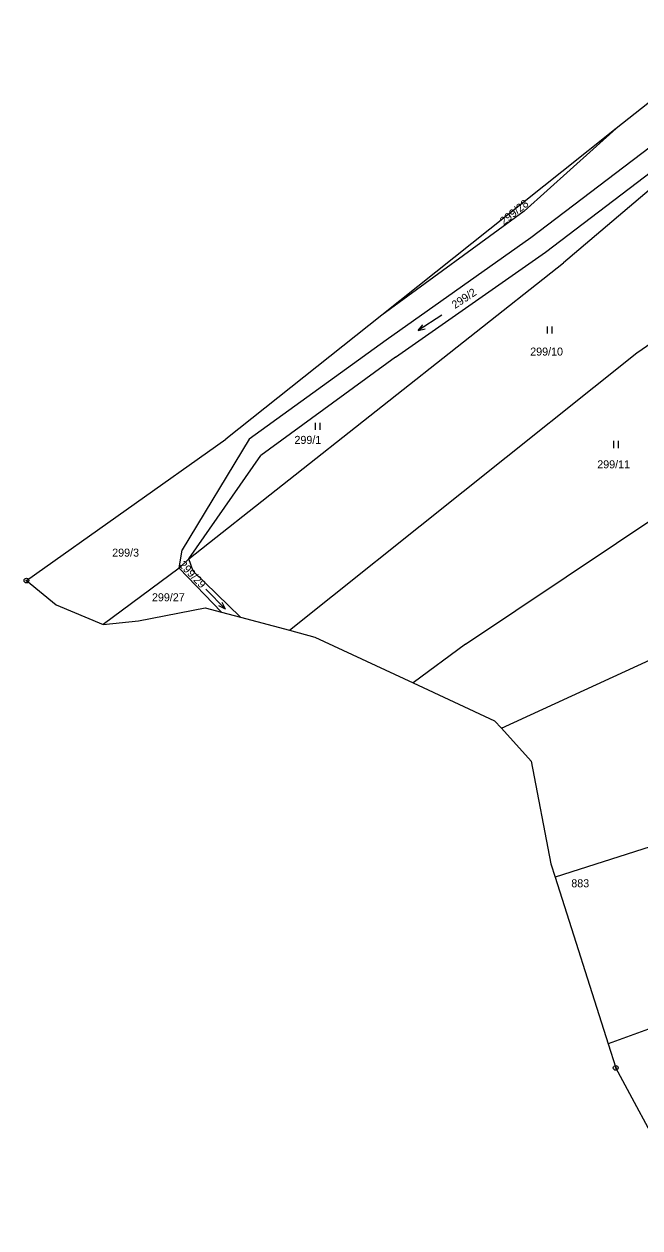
# Model space of a CAD drawing. Extents: x -762263 to -760336, y -1154405 to -1152076.
# Drawn here: x -761628.3 to -761497.7, y -1153957.4 to -1153701.8 of the extents above; entities that cross this region are included whole.
import ezdxf

# ---------------------------------------------------------------- set-up
doc = ezdxf.new("R2010")
doc.units = 0
for name, color, linetype in [('Vrstva 1', 7, 'Continuous'), ('Vrstva 13', 7, 'Continuous'), ('Vrstva 17', 7, 'Continuous'), ('Vrstva 18', 7, 'Continuous'), ('Vrstva 24', 7, 'Continuous'), ('Vrstva 25', 7, 'Continuous'), ('Vrstva 6', 7, 'Continuous')]:
    doc.layers.add(name, color=color, linetype=linetype)

msp = doc.modelspace()

# ---------------------------------------------------------------- linework, layer by layer
at = {"layer": 'Vrstva 1'}
for p, q in [((-761491.67, -1153725), (-761520.83, -1153747.19)), ((-761517.69, -1153750.19), (-761489.51, -1153728.71)), ((-761520.83, -1153747.19), (-761551.47, -1153768.91)), ((-761549.5, -1153772.51), (-761517.69, -1153750.19)), ((-761551.47, -1153768.91), (-761580.6, -1153789.9)), ((-761549.5, -1153772.51), (-761578.13, -1153793.41)), ((-761580.6, -1153789.9), (-761594.82, -1153813.41)), ((-761593.36, -1153815.36), (-761578.13, -1153793.41)), ((-761595.44, -1153817.33), (-761594.82, -1153813.41)), ((-761586.44, -1153826.67), (-761595.44, -1153817.33)), ((-761592.45, -1153817.96), (-761593.36, -1153815.36)), ((-761592.45, -1153817.96), (-761582.4, -1153827.73))]:
    msp.add_line(p, q, dxfattribs=at)
at = {"layer": 'Vrstva 13'}
for p, q in [((-761487.61, -1153711.97), (-761502.71, -1153723.99)), ((-761502.71, -1153723.99), (-761514.21, -1153733.15)), ((-761514.21, -1153733.15), (-761552.42, -1153763.57)), ((-761552.42, -1153763.57), (-761585.55, -1153789.95)), ((-761627.83, -1153819.95), (-761585.55, -1153789.95)), ((-761627.83, -1153819.95), (-761621.55, -1153825.1)), ((-761621.55, -1153825.1), (-761611.57, -1153829.29)), ((-761604.02, -1153828.47), (-761589.93, -1153825.71)), ((-761589.93, -1153825.71), (-761586.44, -1153826.67)), ((-761586.44, -1153826.67), (-761582.4, -1153827.73)), ((-761582.4, -1153827.73), (-761571.98, -1153830.52)), ((-761611.57, -1153829.29), (-761604.02, -1153828.47)), ((-761571.98, -1153830.52), (-761566.67, -1153831.95)), ((-761566.67, -1153831.95), (-761545.76, -1153841.68)), ((-761545.76, -1153841.68), (-761528.48, -1153849.72)), ((-761528.48, -1153849.72), (-761527.03, -1153851.32)), ((-761527.03, -1153851.32), (-761520.72, -1153858.29)), ((-761520.72, -1153858.29), (-761516.55, -1153880.13)), ((-761516.55, -1153880.13), (-761515.66, -1153882.92)), ((-761515.66, -1153882.92), (-761504.41, -1153918.34)), ((-761504.41, -1153918.34), (-761502.8, -1153923.42)), ((-761484.5, -1153957.41), (-761502.8, -1153923.42))]:
    msp.add_line(p, q, dxfattribs=at)
at = {"layer": 'Vrstva 24'}
for centre, radius in [((-761627.83, -1153819.95), 0.5), ((-761627.83, -1153819.95), 0.1), ((-761502.8, -1153923.42), 0.5), ((-761502.8, -1153923.42), 0.1)]:
    msp.add_circle(centre, radius, dxfattribs=at)
at = {"layer": 'Vrstva 25'}
for p, q in [((-761517.3, -1153767.5), (-761517.3, -1153766)), ((-761516.3, -1153767.5), (-761516.3, -1153766)), ((-761566.49, -1153787.96), (-761566.49, -1153786.46)), ((-761565.49, -1153787.96), (-761565.49, -1153786.46)), ((-761503.17, -1153791.81), (-761503.17, -1153790.31)), ((-761502.17, -1153791.81), (-761502.17, -1153790.31))]:
    msp.add_line(p, q, dxfattribs=at)
for points in [[(-761539.696, -1153763.612), (-761544.724, -1153766.888), (-761543.194, -1153766.488)], [(-761544.724, -1153766.888), (-761543.74, -1153765.65)], [(-761589.788, -1153821.766), (-761585.592, -1153826.054), (-761586.283, -1153824.632)], [(-761585.592, -1153826.054), (-761586.998, -1153825.332)]]:
    msp.add_lwpolyline(points, dxfattribs=at)
at = {"layer": 'Vrstva 6'}
for p, q in [((-761454.21, -1153701.79), (-761513.86, -1153752.5)), ((-761522.23, -1153741.49), (-761502.71, -1153723.99)), ((-761522.23, -1153741.49), (-761552.42, -1153763.57)), ((-761498.3, -1153771.59), (-761466.5, -1153749.37)), ((-761593.36, -1153815.36), (-761513.86, -1153752.5)), ((-761571.98, -1153830.52), (-761498.3, -1153771.59)), ((-761534.69, -1153833.47), (-761461.07, -1153784.2)), ((-761527.03, -1153851.32), (-761446.29, -1153814.02)), ((-761595.44, -1153817.33), (-761611.57, -1153829.29)), ((-761593.36, -1153815.36), (-761595.44, -1153817.33)), ((-761534.69, -1153833.47), (-761545.76, -1153841.68)), ((-761472.22, -1153869), (-761515.66, -1153882.92)), ((-761491.88, -1153913.75), (-761504.41, -1153918.34))]:
    msp.add_line(p, q, dxfattribs=at)

# ---------------------------------------------------------------- texts
at = {"layer": 'Vrstva 17'}
msp.add_text('883', height=1.7, dxfattribs=at).set_placement((-761512.214, -1153885.08))
at = {"layer": 'Vrstva 18'}
for s, rotation, p in [('299/28', 38.61736, (-761526.542, -1153744.557)), ('299/2', 33.68992, (-761536.899, -1153762.326)), ('299/29', 313.86628, (-761595.609, -1153816.722))]:
    msp.add_text(s, height=1.7, rotation=rotation, dxfattribs=at).set_placement(p)
for s, p in [('299/10', (-761520.935, -1153772.18)), ('299/1', (-761570.959, -1153790.93)), ('299/11', (-761506.71, -1153796.12)), ('299/3', (-761609.634, -1153814.87)), ('299/27', (-761601.2, -1153824.35))]:
    msp.add_text(s, height=1.7, dxfattribs=at).set_placement(p)

doc.saveas('drawing.dxf')
